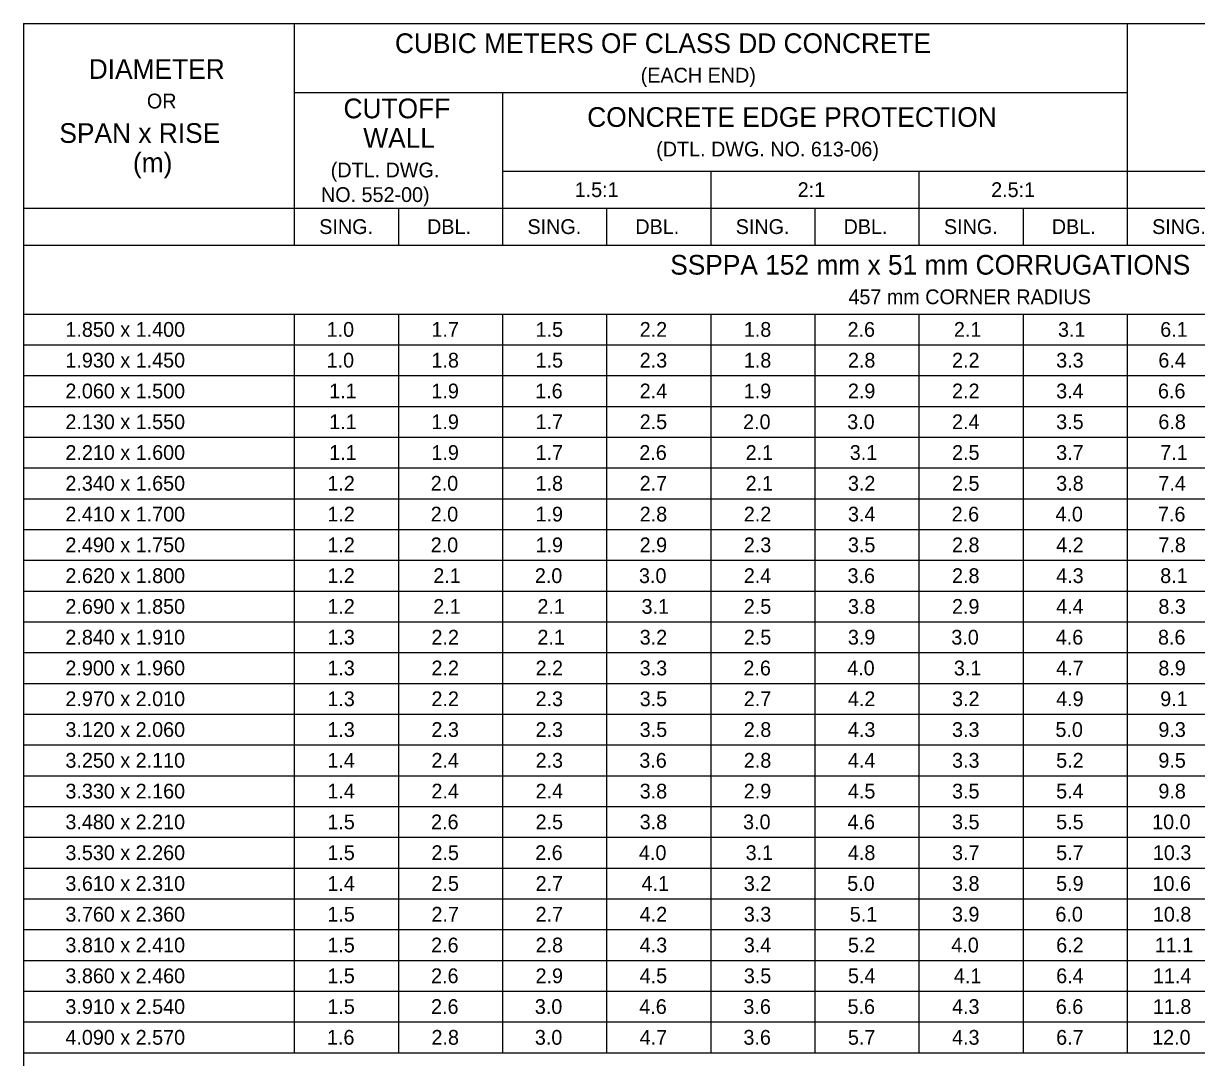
# Model space of a CAD drawing. Extents: x 49991.4 to 50047.6, y 49987.6 to 50011.4.
# Drawn here: x 50031.96 to 50036.728, y 50006.859 to 50011.058 of the extents above; entities that cross this region are included whole.
import ezdxf

# ---------------------------------------------------------------- set-up
doc = ezdxf.new("R2010")
doc.units = 0
doc.layers.add('Level 5', color=7, linetype='Continuous')

msp = doc.modelspace()

# ---------------------------------------------------------------- linework, layer by layer
at = {"layer": 'Level 5'}
for p, q in [((50031.9605, 50011.0583), (50039.8305, 50011.0583)), ((50031.9605, 50011.0583), (50031.9605, 50003.5983)), ((50033.0609, 50011.0583), (50033.0609, 50010.1583)), ((50036.4457, 50011.0583), (50036.4457, 50010.1583)), ((50033.0609, 50010.7783), (50036.4457, 50010.7783)), ((50033.9071, 50010.7783), (50033.9071, 50010.1583)), ((50033.9071, 50010.4583), (50038.9843, 50010.4583)), ((50034.7533, 50010.4583), (50034.7533, 50010.1583)), ((50035.5995, 50010.4583), (50035.5995, 50010.1583)), ((50031.9605, 50010.3083), (50039.8305, 50010.3083)), ((50033.484, 50010.3083), (50033.484, 50010.1583)), ((50034.3302, 50010.3083), (50034.3302, 50010.1583)), ((50035.1764, 50010.3083), (50035.1764, 50010.1583)), ((50036.0226, 50010.3083), (50036.0226, 50010.1583)), ((50031.9605, 50010.1583), (50039.8305, 50010.1583)), ((50031.9605, 50009.8783), (50039.8305, 50009.8783)), ((50033.0609, 50009.8783), (50033.0609, 50006.8783)), ((50033.484, 50009.8783), (50033.484, 50006.8783)), ((50033.9071, 50009.8783), (50033.9071, 50006.8783)), ((50034.3302, 50009.8783), (50034.3302, 50006.8783)), ((50034.7533, 50009.8783), (50034.7533, 50006.8783)), ((50035.1764, 50009.8783), (50035.1764, 50006.8783)), ((50035.5995, 50009.8783), (50035.5995, 50006.8783)), ((50036.0226, 50009.8783), (50036.0226, 50006.8783)), ((50036.4457, 50009.8783), (50036.4457, 50006.8783)), ((50031.9605, 50009.7533), (50039.8305, 50009.7533)), ((50031.9605, 50009.6283), (50039.8305, 50009.6283)), ((50031.9605, 50009.5033), (50039.8305, 50009.5033)), ((50031.9605, 50009.3783), (50039.8305, 50009.3783)), ((50031.9605, 50009.2533), (50039.8305, 50009.2533)), ((50031.9605, 50009.1283), (50039.8305, 50009.1283)), ((50031.9605, 50009.0033), (50039.8305, 50009.0033)), ((50031.9605, 50008.8783), (50039.8305, 50008.8783)), ((50031.9605, 50008.7533), (50039.8305, 50008.7533)), ((50031.9605, 50008.6283), (50039.8305, 50008.6283)), ((50031.9605, 50008.5033), (50039.8305, 50008.5033)), ((50031.9605, 50008.3783), (50039.8305, 50008.3783)), ((50031.9605, 50008.2533), (50039.8305, 50008.2533)), ((50031.9605, 50008.1283), (50039.8305, 50008.1283)), ((50031.9605, 50008.0033), (50039.8305, 50008.0033)), ((50031.9605, 50007.8783), (50039.8305, 50007.8783)), ((50031.9605, 50007.7533), (50039.8305, 50007.7533)), ((50031.9605, 50007.6283), (50039.8305, 50007.6283)), ((50031.9605, 50007.5033), (50039.8305, 50007.5033)), ((50031.9605, 50007.3783), (50039.8305, 50007.3783)), ((50031.9605, 50007.2533), (50039.8305, 50007.2533)), ((50031.9605, 50007.1283), (50039.8305, 50007.1283)), ((50031.9605, 50007.0033), (50039.8305, 50007.0033)), ((50031.9605, 50006.8783), (50039.8305, 50006.8783))]:
    msp.add_line(p, q, dxfattribs=at)

# ---------------------------------------------------------------- texts
for s, height, p in [('CUBIC METERS OF CLASS DD CONCRETE', 0.0799, (50033.4702, 50010.9383)), ('DIAMETER', 0.08, (50032.2257, 50010.8333)), ('(EACH END)', 0.06, (50034.4688, 50010.8183)), ('OR', 0.06, (50032.4621, 50010.7133)), ('CUTOFF', 0.08, (50033.261, 50010.6733)), ('CONCRETE EDGE PROTECTION', 0.08, (50034.2514, 50010.6383)), ('SPAN x RISE', 0.08, (50032.1063, 50010.5733)), ('WALL', 0.08, (50033.3414, 50010.5533)), ('(DTL. DWG. NO. 613-06)', 0.06, (50034.5319, 50010.5183)), ('(m)', 0.08, (50032.4053, 50010.4533)), ('(DTL. DWG.', 0.06, (50033.2092, 50010.4333)), ('NO. 552-00)', 0.06, (50033.1695, 50010.3333)), ('1.5:1', 0.06, (50034.2006, 50010.3533)), ('2:1', 0.06, (50035.1068, 50010.3533)), ('2.5:1', 0.06, (50035.893, 50010.3533)), ('SING.', 0.06, (50033.1625, 50010.2033)), ('DBL.', 0.06, (50033.6008, 50010.2033)), ('SING.', 0.06, (50034.0087, 50010.2033)), ('DBL.', 0.06, (50034.447, 50010.2033)), ('SING.', 0.06, (50034.8549, 50010.2033)), ('DBL.', 0.06, (50035.2932, 50010.2033)), ('SING.', 0.06, (50035.7011, 50010.2033)), ('DBL.', 0.06, (50036.1394, 50010.2033)), ('SING.', 0.06, (50036.5473, 50010.2033)), ('SSPPA 152 mm x 51 mm CORRUGATIONS', 0.0799, (50034.5888, 50010.0383)), ('457 mm CORNER RADIUS', 0.06, (50035.313, 50009.9183)), ('1.850 x 1.400', 0.06, (50032.131, 50009.7858)), ('1.0', 0.06, (50033.1925, 50009.7858)), ('1.7', 0.06, (50033.6186, 50009.7858)), ('1.5', 0.06, (50034.0417, 50009.7858)), ('2.2', 0.06, (50034.4648, 50009.7858)), ('1.8', 0.06, (50034.8879, 50009.7858)), ('2.6', 0.06, (50035.3094, 50009.7858)), ('2.1', 0.06, (50035.7415, 50009.7858)), ('3.1', 0.06, (50036.1646, 50009.7858)), (' 6.1', 0.06, (50036.5577, 50009.7858)), ('1.930 x 1.450', 0.06, (50032.131, 50009.6608)), ('1.0', 0.06, (50033.1925, 50009.6608)), ('1.8', 0.06, (50033.6186, 50009.6608)), ('1.5', 0.06, (50034.0417, 50009.6608)), ('2.3', 0.06, (50034.4648, 50009.6608)), ('1.8', 0.06, (50034.8879, 50009.6608)), ('2.8', 0.06, (50035.311, 50009.6608)), ('2.2', 0.06, (50035.7341, 50009.6608)), ('3.3', 0.06, (50036.1572, 50009.6608)), (' 6.4', 0.06, (50036.5503, 50009.6608)), ('2.060 x 1.500', 0.06, (50032.131, 50009.5358)), ('1.1', 0.06, (50033.2029, 50009.5358)), ('1.9', 0.06, (50033.6184, 50009.5358)), ('1.6', 0.06, (50034.0401, 50009.5358)), ('2.4', 0.06, (50034.4648, 50009.5358)), ('1.9', 0.06, (50034.8877, 50009.5358)), ('2.9', 0.06, (50035.3108, 50009.5358)), ('2.2', 0.06, (50035.7341, 50009.5358)), ('3.4', 0.06, (50036.1572, 50009.5358)), (' 6.6', 0.06, (50036.5487, 50009.5358)), ('2.130 x 1.550', 0.06, (50032.131, 50009.4108)), ('1.1', 0.06, (50033.2029, 50009.4108)), ('1.9', 0.06, (50033.6184, 50009.4108)), ('1.7', 0.06, (50034.0417, 50009.4108)), ('2.5', 0.06, (50034.4648, 50009.4108)), ('2.0', 0.06, (50034.8849, 50009.4108)), ('3.0', 0.06, (50035.308, 50009.4108)), ('2.4', 0.06, (50035.7341, 50009.4108)), ('3.5', 0.06, (50036.1572, 50009.4108)), (' 6.8', 0.06, (50036.5503, 50009.4108)), ('2.210 x 1.600', 0.06, (50032.131, 50009.2858)), ('1.9', 0.06, (50033.6184, 50009.2858)), ('2.6', 0.06, (50034.4632, 50009.2858)), ('2.1', 0.06, (50034.8953, 50009.2858)), ('3.1', 0.06, (50035.3184, 50009.2858)), ('2.5', 0.06, (50035.7341, 50009.2858)), ('3.7', 0.06, (50036.1572, 50009.2858)), ('1.1', 0.06, (50033.2029, 50009.2858)), ('1.7', 0.06, (50034.0417, 50009.2858)), (' 7.1', 0.06, (50036.5577, 50009.2858)), ('2.340 x 1.650', 0.06, (50032.131, 50009.1608)), ('1.2', 0.06, (50033.1955, 50009.1608)), ('2.0', 0.06, (50033.6156, 50009.1608)), ('1.8', 0.06, (50034.0417, 50009.1608)), ('2.7', 0.06, (50034.4648, 50009.1608)), ('2.1', 0.06, (50034.8953, 50009.1608)), ('3.2', 0.06, (50035.311, 50009.1608)), ('2.5', 0.06, (50035.7341, 50009.1608)), ('3.8', 0.06, (50036.1572, 50009.1608)), (' 7.4', 0.06, (50036.5503, 50009.1608)), ('2.410 x 1.700', 0.06, (50032.131, 50009.0358)), ('1.2', 0.06, (50033.1955, 50009.0358)), ('2.0', 0.06, (50033.6156, 50009.0358)), ('1.9', 0.06, (50034.0415, 50009.0358)), ('2.8', 0.06, (50034.4648, 50009.0358)), ('2.2', 0.06, (50034.8879, 50009.0358)), ('3.4', 0.06, (50035.311, 50009.0358)), ('2.6', 0.06, (50035.7325, 50009.0358)), ('4.0', 0.06, (50036.1542, 50009.0358)), (' 7.6', 0.06, (50036.5487, 50009.0358)), ('2.490 x 1.750', 0.06, (50032.131, 50008.9108)), ('1.2', 0.06, (50033.1955, 50008.9108)), ('2.0', 0.06, (50033.6156, 50008.9108)), ('1.9', 0.06, (50034.0415, 50008.9108)), ('2.9', 0.06, (50034.4646, 50008.9108)), ('2.3', 0.06, (50034.8879, 50008.9108)), ('3.5', 0.06, (50035.311, 50008.9108)), ('2.8', 0.06, (50035.7341, 50008.9108)), ('4.2', 0.06, (50036.1572, 50008.9108)), (' 7.8', 0.06, (50036.5503, 50008.9108)), ('2.620 x 1.800', 0.06, (50032.131, 50008.7858)), ('1.2', 0.06, (50033.1955, 50008.7858)), ('2.1', 0.06, (50033.626, 50008.7858)), ('2.0', 0.06, (50034.0387, 50008.7858)), ('3.0', 0.06, (50034.4618, 50008.7858)), ('2.4', 0.06, (50034.8879, 50008.7858)), ('3.6', 0.06, (50035.3094, 50008.7858)), ('2.8', 0.06, (50035.7341, 50008.7858)), ('4.3', 0.06, (50036.1572, 50008.7858)), (' 8.1', 0.06, (50036.5577, 50008.7858)), ('2.690 x 1.850', 0.06, (50032.131, 50008.6608)), ('1.2', 0.06, (50033.1955, 50008.6608)), ('2.1', 0.06, (50033.626, 50008.6608)), ('2.1', 0.06, (50034.0491, 50008.6608)), ('3.1', 0.06, (50034.4722, 50008.6608)), ('2.5', 0.06, (50034.8879, 50008.6608)), ('3.8', 0.06, (50035.311, 50008.6608)), ('2.9', 0.06, (50035.7339, 50008.6608)), ('4.4', 0.06, (50036.1572, 50008.6608)), (' 8.3', 0.06, (50036.5503, 50008.6608)), ('2.840 x 1.910', 0.06, (50032.131, 50008.5358)), ('1.3', 0.06, (50033.1955, 50008.5358)), ('2.2', 0.06, (50033.6186, 50008.5358)), ('2.1', 0.06, (50034.0491, 50008.5358)), ('3.2', 0.06, (50034.4648, 50008.5358)), ('2.5', 0.06, (50034.8879, 50008.5358)), ('3.9', 0.06, (50035.3108, 50008.5358)), ('3.0', 0.06, (50035.7311, 50008.5358)), ('4.6', 0.06, (50036.1556, 50008.5358)), (' 8.6', 0.06, (50036.5487, 50008.5358)), ('2.900 x 1.960', 0.06, (50032.131, 50008.4108)), ('1.3', 0.06, (50033.1955, 50008.4108)), ('2.2', 0.06, (50033.6186, 50008.4108)), ('2.2', 0.06, (50034.0417, 50008.4108)), ('3.3', 0.06, (50034.4648, 50008.4108)), ('2.6', 0.06, (50034.8863, 50008.4108)), ('4.0', 0.06, (50035.308, 50008.4108)), ('3.1', 0.06, (50035.7415, 50008.4108)), ('4.7', 0.06, (50036.1572, 50008.4108)), (' 8.9', 0.06, (50036.5501, 50008.4108)), ('2.970 x 2.010', 0.06, (50032.131, 50008.2858)), ('1.3', 0.06, (50033.1955, 50008.2858)), ('2.2', 0.06, (50033.6186, 50008.2858)), ('2.3', 0.06, (50034.0417, 50008.2858)), ('3.5', 0.06, (50034.4648, 50008.2858)), ('2.7', 0.06, (50034.8879, 50008.2858)), ('4.2', 0.06, (50035.311, 50008.2858)), ('3.2', 0.06, (50035.7341, 50008.2858)), ('4.9', 0.06, (50036.157, 50008.2858)), (' 9.1', 0.06, (50036.5577, 50008.2858)), ('3.120 x 2.060', 0.06, (50032.131, 50008.1608)), ('1.3', 0.06, (50033.1955, 50008.1608)), ('2.3', 0.06, (50033.6186, 50008.1608)), ('2.3', 0.06, (50034.0417, 50008.1608)), ('3.5', 0.06, (50034.4648, 50008.1608)), ('2.8', 0.06, (50034.8879, 50008.1608)), ('4.3', 0.06, (50035.311, 50008.1608)), ('3.3', 0.06, (50035.7341, 50008.1608)), ('5.0', 0.06, (50036.1542, 50008.1608)), (' 9.3', 0.06, (50036.5503, 50008.1608)), ('3.250 x 2.110', 0.06, (50032.131, 50008.0358)), ('1.4', 0.06, (50033.1955, 50008.0358)), ('2.4', 0.06, (50033.6186, 50008.0358)), ('2.3', 0.06, (50034.0417, 50008.0358)), ('3.6', 0.06, (50034.4632, 50008.0358)), ('2.8', 0.06, (50034.8879, 50008.0358)), ('4.4', 0.06, (50035.311, 50008.0358)), ('3.3', 0.06, (50035.7341, 50008.0358)), ('5.2', 0.06, (50036.1572, 50008.0358)), (' 9.5', 0.06, (50036.5503, 50008.0358)), ('3.330 x 2.160', 0.06, (50032.131, 50007.9108)), ('1.4', 0.06, (50033.1955, 50007.9108)), ('2.4', 0.06, (50033.6186, 50007.9108)), ('2.4', 0.06, (50034.0417, 50007.9108)), ('3.8', 0.06, (50034.4648, 50007.9108)), ('2.9', 0.06, (50034.8877, 50007.9108)), ('4.5', 0.06, (50035.311, 50007.9108)), ('3.5', 0.06, (50035.7341, 50007.9108)), ('5.4', 0.06, (50036.1572, 50007.9108)), (' 9.8', 0.06, (50036.5503, 50007.9108)), ('3.480 x 2.210', 0.06, (50032.131, 50007.7858)), ('1.5', 0.06, (50033.1955, 50007.7858)), ('2.6', 0.06, (50033.617, 50007.7858)), ('2.5', 0.06, (50034.0417, 50007.7858)), ('3.8', 0.06, (50034.4648, 50007.7858)), ('3.0', 0.06, (50034.8849, 50007.7858)), ('4.6', 0.06, (50035.3094, 50007.7858)), ('3.5', 0.06, (50035.7341, 50007.7858)), ('5.5', 0.06, (50036.1572, 50007.7858)), ('10.0', 0.06, (50036.5473, 50007.7858)), ('3.530 x 2.260', 0.06, (50032.131, 50007.6608)), ('1.5', 0.06, (50033.1955, 50007.6608)), ('2.5', 0.06, (50033.6186, 50007.6608)), ('2.6', 0.06, (50034.0401, 50007.6608)), ('4.0', 0.06, (50034.4618, 50007.6608)), ('3.1', 0.06, (50034.8953, 50007.6608)), ('4.8', 0.06, (50035.311, 50007.6608)), ('3.7', 0.06, (50035.7341, 50007.6608)), ('5.7', 0.06, (50036.1572, 50007.6608)), ('10.3', 0.06, (50036.5503, 50007.6608)), ('3.610 x 2.310', 0.06, (50032.131, 50007.5358)), ('1.4', 0.06, (50033.1955, 50007.5358)), ('2.5', 0.06, (50033.6186, 50007.5358)), ('2.7', 0.06, (50034.0417, 50007.5358)), ('4.1', 0.06, (50034.4722, 50007.5358)), ('3.2', 0.06, (50034.8879, 50007.5358)), ('5.0', 0.06, (50035.308, 50007.5358)), ('3.8', 0.06, (50035.7341, 50007.5358)), ('5.9', 0.06, (50036.157, 50007.5358)), ('10.6', 0.06, (50036.5487, 50007.5358)), ('3.760 x 2.360', 0.06, (50032.131, 50007.4108)), ('1.5', 0.06, (50033.1955, 50007.4108)), ('2.7', 0.06, (50033.6186, 50007.4108)), ('2.7', 0.06, (50034.0417, 50007.4108)), ('4.2', 0.06, (50034.4648, 50007.4108)), ('3.3', 0.06, (50034.8879, 50007.4108)), ('5.1', 0.06, (50035.3184, 50007.4108)), ('3.9', 0.06, (50035.7339, 50007.4108)), ('6.0', 0.06, (50036.1542, 50007.4108)), ('10.8', 0.06, (50036.5503, 50007.4108)), ('3.810 x 2.410', 0.06, (50032.131, 50007.2858)), ('1.5', 0.06, (50033.1955, 50007.2858)), ('2.6', 0.06, (50033.617, 50007.2858)), ('2.8', 0.06, (50034.0417, 50007.2858)), ('4.3', 0.06, (50034.4648, 50007.2858)), ('3.4', 0.06, (50034.8879, 50007.2858)), ('5.2', 0.06, (50035.311, 50007.2858)), ('4.0', 0.06, (50035.7311, 50007.2858)), ('6.2', 0.06, (50036.1572, 50007.2858)), ('11.1', 0.06, (50036.5577, 50007.2858)), ('3.860 x 2.460', 0.06, (50032.131, 50007.1608)), ('1.5', 0.06, (50033.1955, 50007.1608)), ('2.6', 0.06, (50033.617, 50007.1608)), ('2.9', 0.06, (50034.0415, 50007.1608)), ('4.5', 0.06, (50034.4648, 50007.1608)), ('3.5', 0.06, (50034.8879, 50007.1608)), ('5.4', 0.06, (50035.311, 50007.1608)), ('4.1', 0.06, (50035.7415, 50007.1608)), ('6.4', 0.06, (50036.1572, 50007.1608)), ('11.4', 0.06, (50036.5503, 50007.1608)), ('3.910 x 2.540', 0.06, (50032.131, 50007.0358)), ('1.5', 0.06, (50033.1955, 50007.0358)), ('2.6', 0.06, (50033.617, 50007.0358)), ('3.0', 0.06, (50034.0387, 50007.0358)), ('4.6', 0.06, (50034.4632, 50007.0358)), ('3.6', 0.06, (50034.8863, 50007.0358)), ('5.6', 0.06, (50035.3094, 50007.0358)), ('4.3', 0.06, (50035.7341, 50007.0358)), ('6.6', 0.06, (50036.1556, 50007.0358)), ('11.8', 0.06, (50036.5503, 50007.0358)), ('4.090 x 2.570', 0.06, (50032.131, 50006.9108)), ('1.6', 0.06, (50033.1939, 50006.9108)), ('2.8', 0.06, (50033.6186, 50006.9108)), ('3.0', 0.06, (50034.0387, 50006.9108)), ('4.7', 0.06, (50034.4648, 50006.9108)), ('3.6', 0.06, (50034.8863, 50006.9108)), ('5.7', 0.06, (50035.311, 50006.9108)), ('4.3', 0.06, (50035.7341, 50006.9108)), ('6.7', 0.06, (50036.1572, 50006.9108)), ('12.0', 0.06, (50036.5473, 50006.9108))]:
    msp.add_text(s, height=height, dxfattribs=at).set_placement(p)

doc.saveas('drawing.dxf')
